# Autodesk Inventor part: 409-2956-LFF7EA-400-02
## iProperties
Created: 2010-06
Part Number: 409-2956-LFF7EA-400-02
Material: 1/16"Thk PLASTIC
Document SubType Name: Modeling
Designer: S. Boerckel
Engineer: Steve Boerckel
Mass: 230.369 g
Surface Area: 3121.57 cm^2
Volume: 245.073 cm^3
Density: 0.94 g/cm^3
Description: TAG
SMR: =<Material>
Length: 20.000 in
Wide: 12.000 in
Thickness: 0.063 in
Author: S. Boerckel
Revision Number: 0
Subject: DEMIN WATER FORWARDING PUMP SKID-7EA
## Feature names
1. Extrusion1
2. Hole1
